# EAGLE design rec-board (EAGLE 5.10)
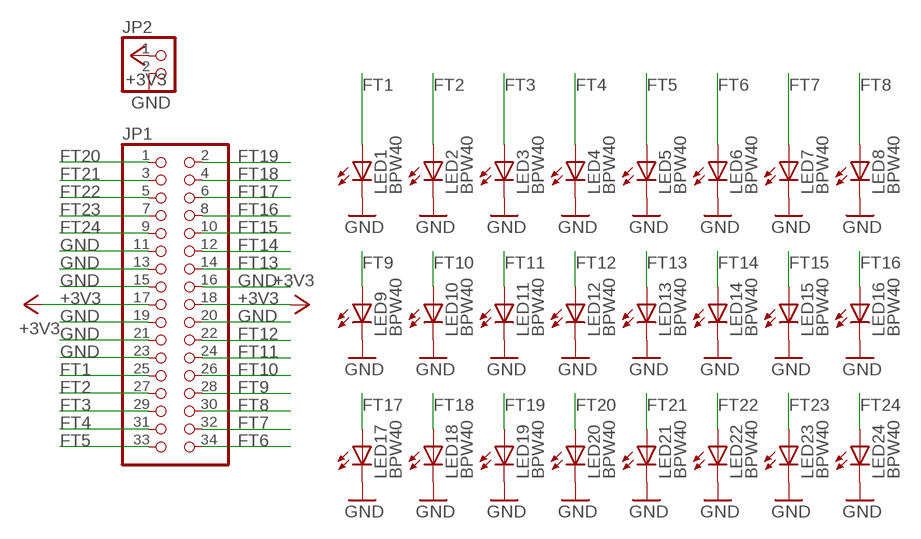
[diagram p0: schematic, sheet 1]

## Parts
JP1  PINHD-2X17  [2X17]
JP2  PINHD-1X2  [1X02]
LED1  BPW40  LED5MM  [LED5MM]
LED2  BPW40  LED5MM  [LED5MM]
LED3  BPW40  LED5MM  [LED5MM]
LED4  BPW40  LED5MM  [LED5MM]
LED5  BPW40  LED5MM  [LED5MM]
LED6  BPW40  LED5MM  [LED5MM]
LED7  BPW40  LED5MM  [LED5MM]
LED8  BPW40  LED5MM  [LED5MM]
LED9  BPW40  LED5MM  [LED5MM]
LED10  BPW40  LED5MM  [LED5MM]
LED11  BPW40  LED5MM  [LED5MM]
LED12  BPW40  LED5MM  [LED5MM]
LED13  BPW40  LED5MM  [LED5MM]
LED14  BPW40  LED5MM  [LED5MM]
LED15  BPW40  LED5MM  [LED5MM]
LED16  BPW40  LED5MM  [LED5MM]
LED17  BPW40  LED5MM  [LED5MM]
LED18  BPW40  LED5MM  [LED5MM]
LED19  BPW40  LED5MM  [LED5MM]
LED20  BPW40  LED5MM  [LED5MM]
LED21  BPW40  LED5MM  [LED5MM]
LED22  BPW40  LED5MM  [LED5MM]
LED23  BPW40  LED5MM  [LED5MM]
LED24  BPW40  LED5MM  [LED5MM]

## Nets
+3V3: JP1.17 JP1.18 JP2.1
FT1: JP1.25 LED1.A
FT2: JP1.27 LED2.A
FT3: JP1.29 LED3.A
FT4: JP1.31 LED4.A
FT5: JP1.33 LED5.A
FT6: JP1.34 LED6.A
FT7: JP1.32 LED7.A
FT8: JP1.30 LED8.A
FT9: JP1.28 LED9.A
FT10: JP1.26 LED10.A
FT11: JP1.24 LED11.A
FT12: JP1.22 LED12.A
FT13: JP1.14 LED13.A
FT14: JP1.12 LED14.A
FT15: JP1.10 LED15.A
FT16: JP1.8 LED16.A
FT17: JP1.6 LED17.A
FT18: JP1.4 LED18.A
FT19: JP1.2 LED19.A
FT20: JP1.1 LED20.A
FT21: JP1.3 LED21.A
FT22: JP1.5 LED22.A
FT23: JP1.7 LED23.A
FT24: JP1.9 LED24.A
GND: JP1.11 JP1.13 JP1.15 JP1.16 JP1.19 JP1.20 JP1.21 JP1.23 JP2.2 LED1.K(C) LED2.K(C) LED3.K(C) LED4.K(C) LED5.K(C) LED6.K(C) LED7.K(C) LED8.K(C) LED9.K(C) LED10.K(C) LED11.K(C) LED12.K(C) LED13.K(C) LED14.K(C) LED15.K(C) LED16.K(C) LED17.K(C) LED18.K(C) LED19.K(C) LED20.K(C) LED21.K(C) LED22.K(C) LED23.K(C) LED24.K(C)

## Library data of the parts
JP1 = pinhead:PINHD-2X17: PIN HEADER
JP2 = pinhead:PINHD-1X2: PIN HEADER
LED1-LED24 = led:LED: LED

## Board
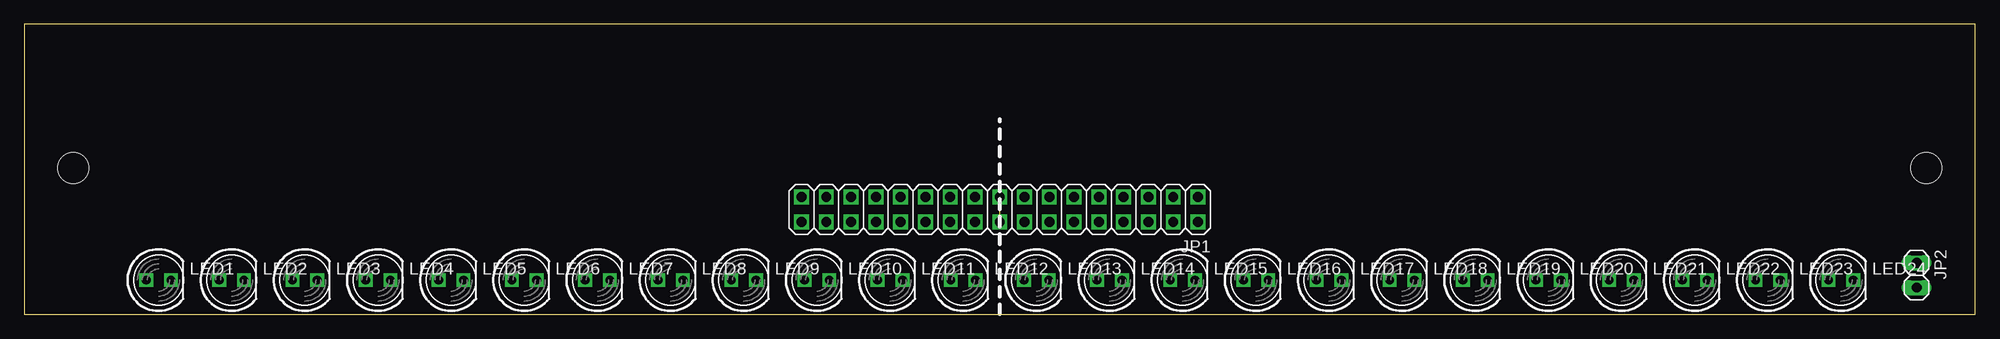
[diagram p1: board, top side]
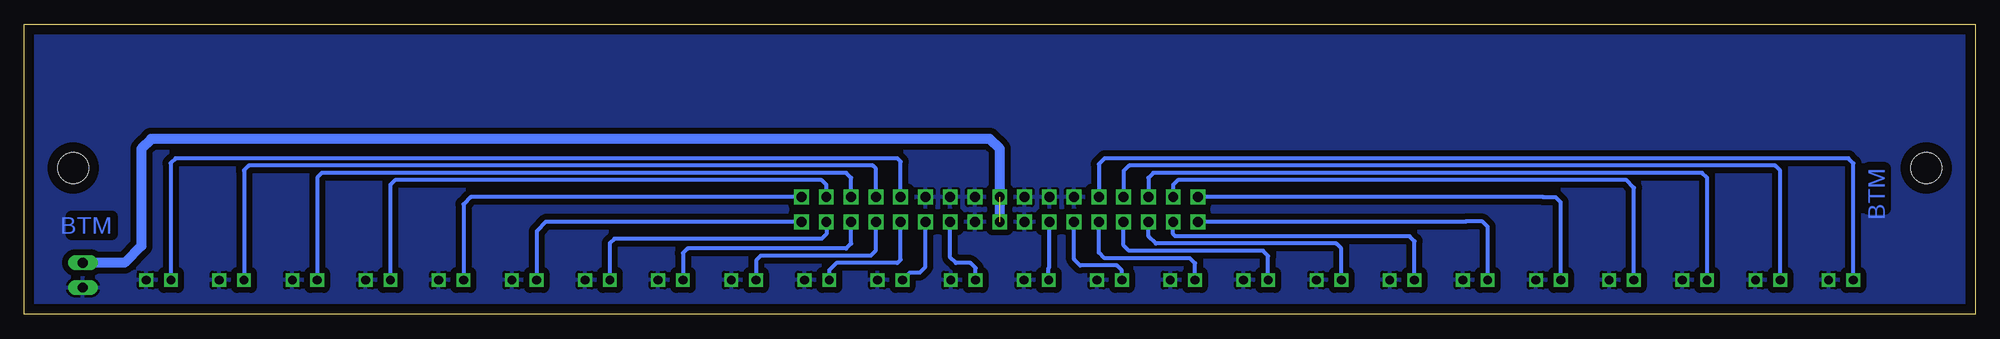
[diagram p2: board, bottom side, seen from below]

Size 200 x 29.75 mm. Coordinates in mm from the lower left corner, seen from the top.
Outline: 0,0 200,0 200,29.75 0,29.75 0,0
Copper layers (1*16): Top 0.035mm / dielectric 1.5mm / Bottom 0.035mm
Design rules "default": minimum track width 10mil, minimum drill 24mil, track to track 8mil, track to pad 8mil, pad to pad 8mil, via to via 8mil, smd to smd 8mil, copper to edge 40mil, drill to drill 8mil, minimum pad ring 10mil, minimum via ring 8mil, stop-mask expansion 4mil, vias tented up to drill 0mil, thermal gap 10mil
Holes 3.2 mm at 5,15 195,15

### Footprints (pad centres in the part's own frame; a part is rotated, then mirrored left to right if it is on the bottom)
2X17 = drill 1.016 square: 1 -20.32,-1.27; 2 -20.32,1.27; 3 -17.78,-1.27; 4 -17.78,1.27; 5 -15.24,-1.27; 6 -15.24,1.27; 7 -12.7,-1.27; 8 -12.7,1.27; 9 -10.16,-1.27; 10 -10.16,1.27; 11 -7.62,-1.27; 12 -7.62,1.27; 13 -5.08,-1.27; 14 -5.08,1.27; 15 -2.54,-1.27; 16 -2.54,1.27; 17 0,-1.27; 18 0,1.27; 19 2.54,-1.27; 20 2.54,1.27; 21 5.08,-1.27; 22 5.08,1.27; 23 7.62,-1.27; 24 7.62,1.27; 25 10.16,-1.27; 26 10.16,1.27; 27 12.7,-1.27; 28 12.7,1.27; 29 15.24,-1.27; 30 15.24,1.27; 31 17.78,-1.27; 32 17.78,1.27; 33 20.32,-1.27; 34 20.32,1.27
1X02 = drill 1.016 long: 1 -1.27,0; 2 1.27,0
LED5MM = drill 0.9 square: A -1.27,0; K 1.27,0

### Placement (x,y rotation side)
JP1  100,10.75 180 top
JP2  194,4 270 top
LED1  13.75,3.5 0 top
LED2  21.25,3.5 0 top
LED3  28.75,3.5 0 top
LED4  36.25,3.5 0 top
LED5  43.75,3.5 0 top
LED6  51.25,3.5 0 top
LED7  58.75,3.5 0 top
LED8  66.25,3.5 0 top
LED9  73.75,3.5 0 top
LED10  81.25,3.5 0 top
LED11  88.75,3.5 0 top
LED12  96.25,3.5 0 top
LED13  103.75,3.5 0 top
LED14  111.25,3.5 0 top
LED15  118.75,3.5 0 top
LED16  126.25,3.5 0 top
LED17  133.75,3.5 0 top
LED18  141.25,3.5 0 top
LED19  148.75,3.5 0 top
LED20  156.25,3.5 0 top
LED21  163.75,3.5 0 top
LED22  171.25,3.5 0 top
LED23  178.75,3.5 0 top
LED24  186.25,3.5 0 top

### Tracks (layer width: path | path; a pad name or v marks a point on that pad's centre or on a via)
+3V3  (1 unrouted)
  Bottom 1.016: JP1.18 100,17 101,18 187,18 188,17 188,7 189.73,5.27 JP2.1
FT1
  Bottom 0.406: JP1.25 89.84,15.41 89.25,16 13,16 12.48,15.48 LED1.A
FT2
  Bottom 0.406: LED2.A 19.98,14.73 20.5,15.25 86.75,15.25 87.3,14.7 JP1.27
FT3
  Bottom 0.406: JP1.29 84.76,13.99 84.25,14.5 28,14.5 27.48,13.98 LED3.A
FT4
  Bottom 0.406: LED4.A 34.98,12.98 35.75,13.75 81.75,13.75 82.22,13.28 JP1.31
FT5
  Bottom 0.406: JP1.33 44.27,12.02 44.25,12 43,12 42.48,11.48 LED5.A
FT6
  Bottom 0.406: JP1.34 52.27,9.48 52.25,9.5 50.5,9.5 49.98,8.98 LED6.A
FT7
  Bottom 0.406: JP1.32 82.22,8.22 82,8 58,8 57.48,7.48 LED7.A
FT8
  Bottom 0.406: LED8.A 64.98,6.73 65.5,7.25 84,7.25 84.75,8 JP1.30
FT9
  Bottom 0.406: LED9.A 72.48,5.98 73,6.5 86.75,6.5 87.3,7.05 JP1.28
FT10
  Bottom 0.406: LED10.A 79.98,5.23 80.5,5.75 89.25,5.75 89.84,6.34 JP1.26
FT11
  Bottom 0.406: LED11.A 87.48,4.48 88,5 91.75,5 92.38,5.63 JP1.24
FT12
  Bottom 0.406: JP1.22 94.92,4.83 95,4.75 95,3.52 LED12.A
FT13
  Bottom 0.406: JP1.14 105.08,5.83 104.5,5.25 103,5.25 102.48,4.73 LED13.A
FT14
  Bottom 0.406: JP1.12 107.62,4.88 108.25,4.25 109.25,4.25 109.98,3.52 LED14.A
FT15
  Bottom 0.406: JP1.10 110.16,5.59 110.5,5.25 116.75,5.25 117.48,4.52 LED15.A
FT16
  Bottom 0.406: JP1.8 112.7,6.55 113.25,6 124.5,6 124.98,5.52 LED16.A
FT17
  Bottom 0.406: JP1.6 115.24,7.26 115.75,6.75 132,6.75 132.48,6.27 LED17.A
FT18
  Bottom 0.406: JP1.4 117.78,8.22 118.25,7.75 139.5,7.75 139.98,7.27 LED18.A
FT19
  Bottom 0.406: JP1.2 146.48,9.48 146.5,9.5 147.48,8.52 LED19.A
FT20
  Bottom 0.406: JP1.1 154.23,12.02 154.98,11.27 LED20.A
FT21
  Bottom 0.406: JP1.3 117.78,13.28 118.25,13.75 162,13.75 162.48,13.27 LED21.A
FT22
  Bottom 0.406: JP1.5 115.24,13.99 115.75,14.5 169.5,14.5 169.98,14.02 LED22.A
FT23
  Bottom 0.406: JP1.7 112.7,14.95 113,15.25 177,15.25 177.5,14.75 177.48,14.73 LED23.A
FT24
  Bottom 0.406: JP1.9 110.16,15.66 110.5,16 184.5,16 185,15.5 185,3.52 LED24.A
GND
  pour Bottom (isolate 0.61): 0,29.75 0,0 200,0 200,29.75

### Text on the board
Bottom: BTM | BTM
